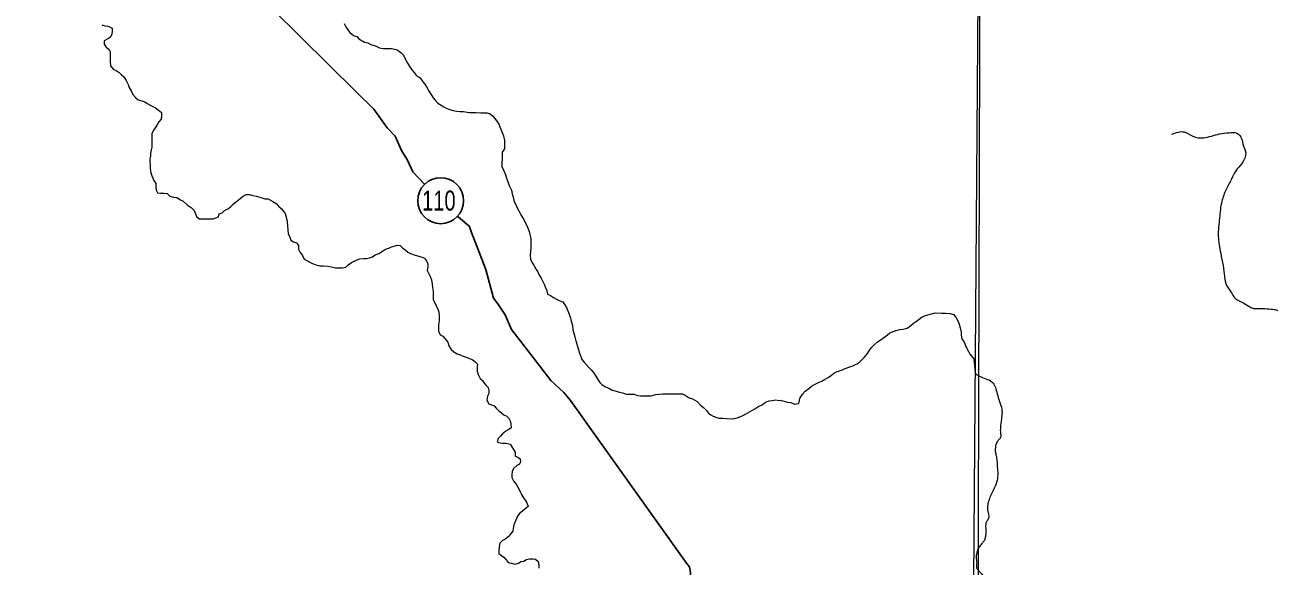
# Model space of a CAD drawing. Extents: x 553962 to 842807, y 8883888 to 9032388.
# Drawn here: x 615180 to 619526, y 8901086 to 8902976 of the extents above; entities that cross this region are included whole.
import ezdxf
from ezdxf.enums import TextEntityAlignment as Align

# ---------------------------------------------------------------- set-up
doc = ezdxf.new("R2010")
doc.units = 0
doc.header["$LTSCALE"] = 200
doc.layers.add('6', color=7, linetype='Continuous', lineweight=13)

msp = doc.modelspace()

# ---------------------------------------------------------------- linework, layer by layer
at = {"layer": '6'}
for points in [[(618663, 8924716.1), (618558.3, 8909803.7), (618456.5, 8896026.7)], [(615448.2, 8902976.6), (615458.4, 8902973.4), (615470.6, 8902971.3), (615484.8, 8902965.1), (615484.7, 8902953.9), (615483.6, 8902943.7), (615478.4, 8902933.6), (615469.2, 8902927.5), (615457, 8902920.5), (615456.9, 8902909.3), (615464, 8902898), (615473.1, 8902891.8), (615478.1, 8902881.6), (615478, 8902868.4), (615477.9, 8902850.1), (615478.8, 8902833.7), (615487.8, 8902821.5), (615499, 8902817.3), (615509.1, 8902810.1), (615517.2, 8902801.9), (615525.3, 8902794.7), (615533.3, 8902782.5), (615540.4, 8902768.2), (615544.4, 8902757.9), (615552.4, 8902743.6), (615556.4, 8902733.4), (615565.5, 8902722.2), (615575.6, 8902715), (615587.8, 8902710.8), (615598.9, 8902707.7), (615607, 8902701.5), (615622.2, 8902693.3), (615636.4, 8902687.1), (615645.5, 8902679.9), (615656.7, 8902670.7), (615656.6, 8902659.5), (615655.5, 8902647.2), (615647.3, 8902638.1), (615643.2, 8902629), (615637, 8902619.9), (615629.8, 8902609.7), (615623.6, 8902596.5), (615623.5, 8902585.3), (615623.4, 8902570), (615623.3, 8902559.8), (615623.3, 8902549.7), (615620.2, 8902539.5), (615618.1, 8902528.3), (615618, 8902518.1), (615615.9, 8902507.9), (615615.8, 8902497.8), (615616.7, 8902486.5), (615617.7, 8902476.3), (615618.6, 8902464.1), (615623.6, 8902448.8), (615629.6, 8902432.5), (615636.6, 8902422.2), (615637.6, 8902409), (615638.5, 8902398.8), (615642.5, 8902389.6), (615653.7, 8902388.5), (615665.9, 8902388.4), (615677.1, 8902387.3), (615686.2, 8902378.1), (615698.4, 8902375), (615710.6, 8902372.9), (615723.7, 8902365.7), (615732.8, 8902360.5), (615746, 8902348.2), (615760.2, 8902337.9), (615771.3, 8902327.7), (615775.3, 8902316.4), (615779.3, 8902307.3), (615788.4, 8902299.1), (615800.6, 8902299), (615811.8, 8902298.9), (615825, 8902298.8), (615837.2, 8902298.8)], [(616295.1, 8902981.4), (616301.1, 8902969.1), (616307.2, 8902959.9), (616315.2, 8902949.7), (616327.9, 8902939.1), (616339.5, 8902936.3), (616346.3, 8902927.4), (616366.4, 8902915.6), (616378.1, 8902914), (616388.1, 8902907.3)], [(616388.1, 8902907.3), (616406.5, 8902902.2), (616418.2, 8902895.6), (616431.6, 8902893.9), (616441.7, 8902893.9), (616460.1, 8902893.9), (616476.8, 8902890.5), (616482.6, 8902888.5), (616493.8, 8902879.2), (616501.8, 8902870), (616510.9, 8902852.7), (616515.9, 8902842.4), (616524, 8902830.2), (616532, 8902818.9), (616539.1, 8902809.7), (616546.1, 8902800.5), (616560.3, 8902791.2), (616570.4, 8902777.9), (616577.4, 8902768.7), (616582.5, 8902759.5), (616591.5, 8902743.1), (616599.6, 8902730.8), (616605.6, 8902721.6), (616612.7, 8902713.4), (616622.8, 8902703.2), (616633.9, 8902696), (616643, 8902689.8), (616651.3, 8902684.9), (616664.3, 8902680.5), (616674.5, 8902677.4), (616688.7, 8902675.3), (616698.9, 8902674.2), (616712.1, 8902674.1), (616730.4, 8902669.9), (616742.6, 8902669.8), (616754.8, 8902669.7), (616772.1, 8902669.6), (616784.3, 8902669.6), (616794.5, 8902669.5), (616805.6, 8902665.3), (616813.7, 8902658.2), (616820.8, 8902651), (616828.8, 8902639.7), (616834.9, 8902629.5), (616838.9, 8902620.3), (616844.9, 8902606), (616851.9, 8902588.6), (616854.8, 8902572.3), (616854.7, 8902555), (616854.6, 8902543.8), (616847.4, 8902531.6), (616847.3, 8902519.4), (616847.2, 8902508.2), (616846.1, 8902492.9), (616846.1, 8902481.7), (616853.1, 8902466.4), (616858.1, 8902452.1), (616863, 8902437.8), (616868, 8902425.5), (616872, 8902415.3), (616879.1, 8902399), (616882, 8902385.7), (616885, 8902374.5), (616888, 8902363.3), (616896, 8902345.9)], [(615837.2, 8902298.8), (615856, 8902306.1), (615858.1, 8902316.3), (615869.3, 8902320.3), (615877.5, 8902327.4), (615890.8, 8902334.4), (615898.9, 8902341.5), (615906.1, 8902348.6), (615915.3, 8902356.7), (615923.5, 8902362.8), (615931.7, 8902369.8), (615941.9, 8902377.9), (615952.1, 8902384), (615964.3, 8902383.9), (615976.5, 8902380.8), (615988.7, 8902377.6)], [(615988.7, 8902377.6), (616003.4, 8902372.8), (616017.6, 8902368.7), (616029.8, 8902368.6), (616046, 8902359.3), (616057.2, 8902352.1), (616066.2, 8902342.9), (616075.3, 8902334.7), (616081.4, 8902326.5), (616088.5, 8902317.3), (616092.4, 8902305), (616095.4, 8902289.7), (616097.3, 8902274.4), (616098.2, 8902260.2), (616099.2, 8902247.9), (616105.2, 8902234.7), (616109.2, 8902224.4), (616118.3, 8902218.3), (616128.4, 8902215.2), (616135.5, 8902205.9), (616135.4, 8902192.7), (616141.4, 8902181.5), (616149.5, 8902170.2), (616155.5, 8902157.9), (616184.9, 8902142.5), (616196.1, 8902138.3), (616210.3, 8902135.2), (616221.5, 8902135.1), (616237.7, 8902134), (616250.9, 8902130.8), (616264.2, 8902127.7), (616274.3, 8902127.6), (616289.6, 8902127.5), (616300.8, 8902129.5), (616309, 8902137.6), (616321.2, 8902146.7), (616336.6, 8902154.7), (616349.8, 8902158.7), (616363, 8902159.7), (616373.2, 8902160.6), (616383.4, 8902162.6), (616393.6, 8902166.6), (616402.8, 8902172.7), (616416.1, 8902177.7), (616429.3, 8902185.7), (616439.6, 8902192.8), (616450.8, 8902196.8), (616460, 8902200.8), (616470.2, 8902203.8), (616480.3, 8902206.8), (616490.5, 8902205.7), (616498.6, 8902197.5), (616507.7, 8902190.3), (616517.8, 8902182.1), (616526.9, 8902178), (616539.1, 8902172.8), (616551.3, 8902169.7), (616563.5, 8902166.5), (616575.7, 8902161.3), (616582.7, 8902152.1), (616587.7, 8902141.9), (616587.7, 8902130.7), (616584.5, 8902118.5), (616590.5, 8902106.2), (616595.6, 8902097)], [(616896, 8902345.9), (616900, 8902336.7), (616905, 8902326.5), (616912, 8902312.2), (616920.1, 8902299.9), (616927.1, 8902286.6), (616936.1, 8902269.2), (616941.1, 8902254.9), (616944.1, 8902243.7), (616947.1, 8902230.4), (616947, 8902218.2), (616946.9, 8902207), (616946.8, 8902196.8), (616945.7, 8902184.6), (616944.6, 8902172.4), (616945.6, 8902158.1), (616951.6, 8902144.8), (616958.6, 8902134.6), (616965.7, 8902122.3), (616971.7, 8902114.1), (616975.7, 8902101.9), (616982.7, 8902091.7), (616988.8, 8902079.4), (616993.8, 8902070.2), (616997.8, 8902061), (617002.8, 8902047.7), (617005.7, 8902035.5), (617015.9, 8902031.3), (617026, 8902024.1), (617037.2, 8902018), (617046.3, 8902013.8), (617058.5, 8902008.7), (617066.5, 8901998.4), (617071.5, 8901989.2), (617076.5, 8901976.9), (617081.6, 8901965.7), (617085.5, 8901952.4)], [(616595.6, 8902097), (616600.6, 8902085.8), (616602.5, 8902070.5), (616603.4, 8902060.3), (616606.4, 8902046), (616606.3, 8902035.8), (616606.2, 8902016.5), (616610.2, 8902007.3), (616616.2, 8901995), (616622.2, 8901982.8), (616625.2, 8901972.6), (616627.2, 8901958.3), (616627.1, 8901943), (616624.9, 8901928.8), (616624.8, 8901917.6), (616624.8, 8901906.3), (616630.8, 8901894.1), (616639.9, 8901888.9), (616647, 8901880.7), (616657.1, 8901868.4), (616661, 8901855.2), (616669.1, 8901842.9), (616678.2, 8901833.7)], [(617085.5, 8901952.4), (617088.5, 8901941.2), (617092.5, 8901925.9), (617094.4, 8901910.6), (617097.4, 8901899.4), (617101.3, 8901886.1), (617104.3, 8901872.9), (617109.3, 8901857.6), (617113.2, 8901841.2), (617117.2, 8901829), (617122.2, 8901817.7), (617125.2, 8901807.5), (617132.3, 8901799.3), (617141.4, 8901789.1), (617150.5, 8901778.8), (617157.5, 8901771.7), (617164.6, 8901763.5), (617173.7, 8901749.1), (617180.7, 8901737.9), (617187.7, 8901726.6), (617196.8, 8901718.4), (617208, 8901712.2), (617219.1, 8901707.1), (617229.3, 8901701.9), (617240.4, 8901697.8), (617256.7, 8901693.6), (617267.8, 8901690.5), (617281, 8901686.3), (617293.2, 8901686.2), (617308.5, 8901686.1), (617319.7, 8901682), (617330.8, 8901680.9), (617345.1, 8901680.8), (617355.3, 8901680.7), (617367.5, 8901680.7), (617383.8, 8901684.6), (617396, 8901686.6), (617407.2, 8901687.5), (617422.5, 8901687.4), (617437.7, 8901687.3), (617454, 8901687.2), (617464.2, 8901687.2), (617477.4, 8901687.1), (617486.5, 8901682.9), (617500.7, 8901673.7), (617511.8, 8901669.6), (617528.1, 8901660.3), (617540.2, 8901648), (617550.3, 8901639.8), (617560.4, 8901629.5), (617567.5, 8901620.3), (617575.6, 8901614.1), (617584.7, 8901610), (617593.8, 8901605.9), (617604, 8901602.7), (617618.2, 8901602.6), (617630.4, 8901601.6), (617646.7, 8901600.4), (617659.9, 8901601.4), (617671.1, 8901605.4), (617685.4, 8901610.4), (617697.6, 8901616.4), (617713, 8901625.5), (617730.3, 8901635.6), (617743.6, 8901644.6)], [(617882.8, 8901653.4), (617884.2, 8901658.2), (617887.4, 8901671.5), (617896.6, 8901686.7), (617905.8, 8901696.8), (617918.1, 8901705.9), (617927.3, 8901714), (617937.6, 8901720), (617951.8, 8901727.1), (617964.1, 8901732.1), (617973.3, 8901737.1), (617985.5, 8901744.2), (617997.8, 8901752.3), (618006, 8901759.3), (618015.2, 8901764.4), (618035.6, 8901771.4), (618045.8, 8901776.4), (618061.1, 8901781.4), (618072.3, 8901785.4), (618081.5, 8901789.4), (618091.7, 8901794.4), (618100.9, 8901803.6), (618112.2, 8901814.7), (618123.4, 8901827.9), (618129.6, 8901838), (618137.8, 8901849.2), (618145, 8901857.3), (618158.3, 8901869.4), (618171.6, 8901877.5), (618183.8, 8901886.6), (618193.1, 8901893.6), (618201.2, 8901900.7), (618212.5, 8901904.7), (618222.7, 8901908.7), (618235.9, 8901912.7), (618248.1, 8901913.7), (618261.4, 8901916.6), (618274.7, 8901925.7), (618283.9, 8901933.8), (618294.1, 8901941.9), (618304.3, 8901948.9), (618314.5, 8901956), (618329.8, 8901962), (618347.2, 8901967), (618359.4, 8901970), (618382.8, 8901969.8), (618396, 8901969.8), (618411.3, 8901968.6), (618423.4, 8901964.5), (618431.5, 8901955.3), (618438.5, 8901942), (618443.6, 8901930.7), (618447.5, 8901918.5), (618450.5, 8901903.2), (618450.4, 8901892), (618453.4, 8901879.7), (618461.4, 8901868.5), (618468.4, 8901850.1), (618476.5, 8901834.8), (618480.5, 8901825.6), (618487.5, 8901818.4), (618494.6, 8901809.2), (618499, 8901761.6)], [(616678.2, 8901833.7), (616690.3, 8901827.5), (616700.5, 8901823.3), (616710.6, 8901819.2), (616720.8, 8901816.1), (616729.9, 8901811.9), (616742.1, 8901807.8), (616751.2, 8901800.6), (616760.3, 8901791.4), (616760.2, 8901780.2), (616760.1, 8901766.9), (616763.1, 8901754.7), (616770.1, 8901741.4), (616778.2, 8901734.2), (616784.2, 8901725), (616791.3, 8901716.8), (616798.4, 8901709.6), (616800.3, 8901699.4), (616800.3, 8901688.2), (616796.1, 8901679.1), (616794, 8901665.8), (616800, 8901652.6), (616810.2, 8901649.4), (616819.3, 8901645.3), (616826.4, 8901637.1), (616835.5, 8901627.9), (616844.6, 8901621.7), (616852.7, 8901614.5), (616862.8, 8901609.4), (616869.9, 8901602.2), (616874.9, 8901593), (616876.8, 8901582.8), (616878.8, 8901568.5), (616870.6, 8901562.5), (616859.4, 8901557.4), (616848.1, 8901548.3), (616840.9, 8901539.2), (616832.8, 8901531.1), (616829.6, 8901519.9), (616834.3, 8901517)], [(617743.6, 8901644.6), (617754.8, 8901648.6), (617767.1, 8901658.7), (617779.9, 8901663.6), (617790.1, 8901664.4), (617803.5, 8901666), (617813.7, 8901664.4), (617818.3, 8901665.2), (617827.8, 8901663.6), (617844.2, 8901658.9), (617856, 8901657.3), (617867.8, 8901651.8), (617882.8, 8901653.4)], [(616834.3, 8901517), (616847.9, 8901514.7), (616860.7, 8901515), (616874.9, 8901511.8), (616892, 8901483.2), (616891.9, 8901470), (616902.1, 8901466.8), (616910.2, 8901460.7), (616911.1, 8901450.5), (616907, 8901441.3), (616897.8, 8901437.3), (616886.6, 8901427.2), (616881.4, 8901416.1), (616881.3, 8901405.9), (616881.2, 8901394.7), (616888.3, 8901381.4), (616896.3, 8901372.1), (616905.4, 8901355.8), (616909.4, 8901345.6), (616914.4, 8901335.3), (616921.5, 8901324.1), (616927.5, 8901315.9), (616933.5, 8901306.7), (616937.5, 8901293.4), (616926.3, 8901284.3), (616918.1, 8901277.3), (616908.9, 8901271.2), (616900.7, 8901260.1), (616893.4, 8901243.8), (616888.2, 8901229.6), (616885.1, 8901217.4), (616884, 8901207.2), (616875.8, 8901197.1), (616867.6, 8901187.9), (616859.4, 8901180.8), (616848.2, 8901174.8), (616839, 8901165.7), (616836.9, 8901153.5), (616835.8, 8901140.2), (616835.7, 8901130.1), (616844.8, 8901122.9), (616852.9, 8901116.7), (616861, 8901107.5), (616868, 8901098.3), (616879.2, 8901096.2), (616891.4, 8901093), (616903.6, 8901096), (616912.8, 8901102.1), (616923, 8901103), (616932.2, 8901109.1), (616942.4, 8901111), (616953.6, 8901111), (616963.7, 8901109.9), (616972.8, 8901101.7), (616974.8, 8901090.5), (616974.7, 8901078.2)]]:
    msp.add_lwpolyline(points, dxfattribs=at)
msp.add_lwpolyline([(618535.2, 8909853.3), (607574.3, 8909890.7), (607543.3, 8898835.3), (618504.2, 8898795.8)], close=True, dxfattribs=at)
at = {"layer": '6', "lineweight": 25}
for points in [[(616044.3, 8903031.2), (616338.7, 8902741.3), (616398.6, 8902682.1), (616445.2, 8902616.8), (616473.6, 8902587.2), (616494.9, 8902537.3), (616516.1, 8902503.6), (616535.3, 8902462.8), (616575.3, 8902420.1)], [(616692.6, 8902307.3), (616726.2, 8902278.1), (616732.3, 8902274), (616740.4, 8902251.6), (616789.8, 8902122.1), (616817, 8902022.2), (616832.2, 8902001.8)], [(616832.2, 8902001.8), (616857.5, 8901964), (616879.7, 8901912), (616954.8, 8901814.1), (617016.6, 8901733.5), (617062.3, 8901691.6), (617085.6, 8901664.1), (617491.1, 8901095.8), (617501.2, 8901082.6), (617505.2, 8901061.2), (617519.8, 8900868.6), (617561, 8900712.6), (617580, 8900602.6), (617583.9, 8900553.7), (617583.7, 8900508.8), (617579.5, 8900483.4), (617569.1, 8900420.2), (617561.6, 8900327.5), (617544.5, 8899823.2), (617553.6, 8899807.9), (617563.8, 8899799.8), (617571, 8899793.8)]]:
    msp.add_lwpolyline(points, dxfattribs=at)
msp.add_circle((616632.2, 8902362.2), 80.3, dxfattribs=at)
at = {"layer": '6'}
for points in [[(619185.4, 8902594.1), (619229.7, 8902602.4), (619260.2, 8902587.2), (619297.6, 8902581.7), (619353, 8902595.5), (619386.3, 8902599.7), (619414, 8902598.3), (619430.6, 8902577.5), (619434.8, 8902560.9), (619444.5, 8902529), (619432, 8902493), (619409.8, 8902466.7), (619394.6, 8902437.6), (619376.6, 8902401.6), (619361.3, 8902360), (619353, 8902301.8), (619348.9, 8902238.1), (619357.2, 8902178.5), (619365.5, 8902135.6), (619371, 8902096.8), (619378, 8902066.3), (619391.8, 8902045.5), (619408.4, 8902020.6), (619436.2, 8902005.4), (619472.2, 8901986), (619504, 8901986), (619533.1, 8901983.2), (619552.5, 8901980.4), (619581.6, 8901952.7), (619601, 8901927.8), (619628.7, 8901891.8), (619645.3, 8901864.1), (619663.3, 8901839.1), (619663.3, 8901812.8), (619663.8, 8901792.9), (619665.6, 8901776.9), (619669.4, 8901761.8), (619673.2, 8901744.9), (619684, 8901732.2), (619697.6, 8901723.7), (619722.6, 8901713.8), (619749.9, 8901713.4), (619772.4, 8901712.4), (619785.6, 8901712.4), (619810.1, 8901719), (619828.4, 8901722.8), (619849.6, 8901727.5), (619870.3, 8901732.2), (619891.9, 8901732.7), (619914.5, 8901727.5), (619939.5, 8901714.3), (619956.4, 8901704), (619975.7, 8901693.2), (619996.4, 8901679), (620013.8, 8901663.5)], [(618499, 8901761.6), (618503.2, 8901756.5), (618514.3, 8901749.3), (618537.3, 8901740.1), (618557.5, 8901729.9), (618566, 8901718.5), (618573.2, 8901700), (618580, 8901674.2), (618589.5, 8901646.4), (618593.3, 8901621.8), (618591.2, 8901598.9), (618587.7, 8901571.1), (618588.4, 8901548.8), (618589.1, 8901537), (618583.5, 8901528.6), (618575.9, 8901520.3), (618571, 8901505), (618569.5, 8901492.9), (618571.1, 8901478.9), (618575.3, 8901458.1), (618576.3, 8901438.2), (618578.3, 8901414.3), (618577.9, 8901397.7), (618572.6, 8901372.7), (618558.5, 8901343), (618550.3, 8901324.2), (618544.1, 8901303.3), (618542.6, 8901289.4), (618545.9, 8901266.5), (618547.2, 8901256.2), (618542, 8901245.6), (618537.3, 8901235.3), (618536.4, 8901218.2), (618537.1, 8901203.9), (618535, 8901190.1), (618531.9, 8901176.4), (618524.9, 8901167.3), (618516, 8901155.2), (618510.6, 8901147.1), (618506.1, 8901139.1), (618505.3, 8901129.8), (618503, 8901122.9), (618503.4, 8901111.4), (618504.7, 8901093.6), (618504.2, 8901080), (618511.5, 8901070.3), (618519.3, 8901061), (618531.9, 8901048.2), (618539.3, 8901039.7), (618544.9, 8901022.6), (618545.9, 8901009.7), (618545.5, 8901001.1), (618542, 8900989.9), (618540.8, 8900979.8), (618540.4, 8900969.7)]]:
    msp.add_spline(points, degree=3, dxfattribs=at)

# ---------------------------------------------------------------- texts
at = {"layer": '6', "width": 0.75}
msp.add_text('110', height=70, dxfattribs=at).set_placement((616625.8, 8902327.6), align=Align.CENTER)

doc.saveas('drawing.dxf')
